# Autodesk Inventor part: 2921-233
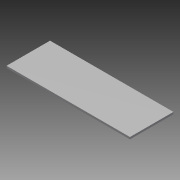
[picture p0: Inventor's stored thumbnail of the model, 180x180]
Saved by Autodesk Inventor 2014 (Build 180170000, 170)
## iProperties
Company: NHTSA/VRTC
Created: 2012-08
Part Number: 2921-233
Material: Steel, Mild
Document SubType Name: Modeling
Designer: Mike Vanvoorhis
Density: 7.86 g/cm^3
Mass: 2639.44 g
Surface Area: 1124.19 cm^2
Volume: 335.807 cm^3
Project: CHILD SIDE IMPACT SLED
Description: HONEYCOMB FRAME BACK PLATE
Stock Number: PL 6.4 (1/4") x 136.5 (5 3/8") x 387.4 (15 1/4")
Appearance: Steel
Vendor: 3
Author: Dave Walker
Title: Honeycomb Frame Back Plate
Subject: Child Side Impact Sled
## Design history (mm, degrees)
sketch "Sketch1"
  geometry: L1 (0, 0)-(387.35, 0); L2 (387.35, 0)-(387.35, 6.35); L3 (387.35, 6.35)-(0, 6.35); L4 (0, 6.35)-(0, 0)
  constraints: 8 end point, 2 parallel, 1 horizontal, 1 perpendicular
  dimensions: "d0" = 387.35 distance of L3.end L2.end; "d1" = 6.35 distance of L2.end L1.end
extrude "Extrusion1" new body sketch "Sketch1" distance "d2" = 136.525; taper "d3" = 0 deg
body "Solid1"
